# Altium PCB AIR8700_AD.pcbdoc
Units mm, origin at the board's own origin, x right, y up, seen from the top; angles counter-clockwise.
Board outline 36 x 42 mm, 2 copper layers (Top Layer, Bottom Layer); 1 components, 0 nets, 70 pads, 0 vias.
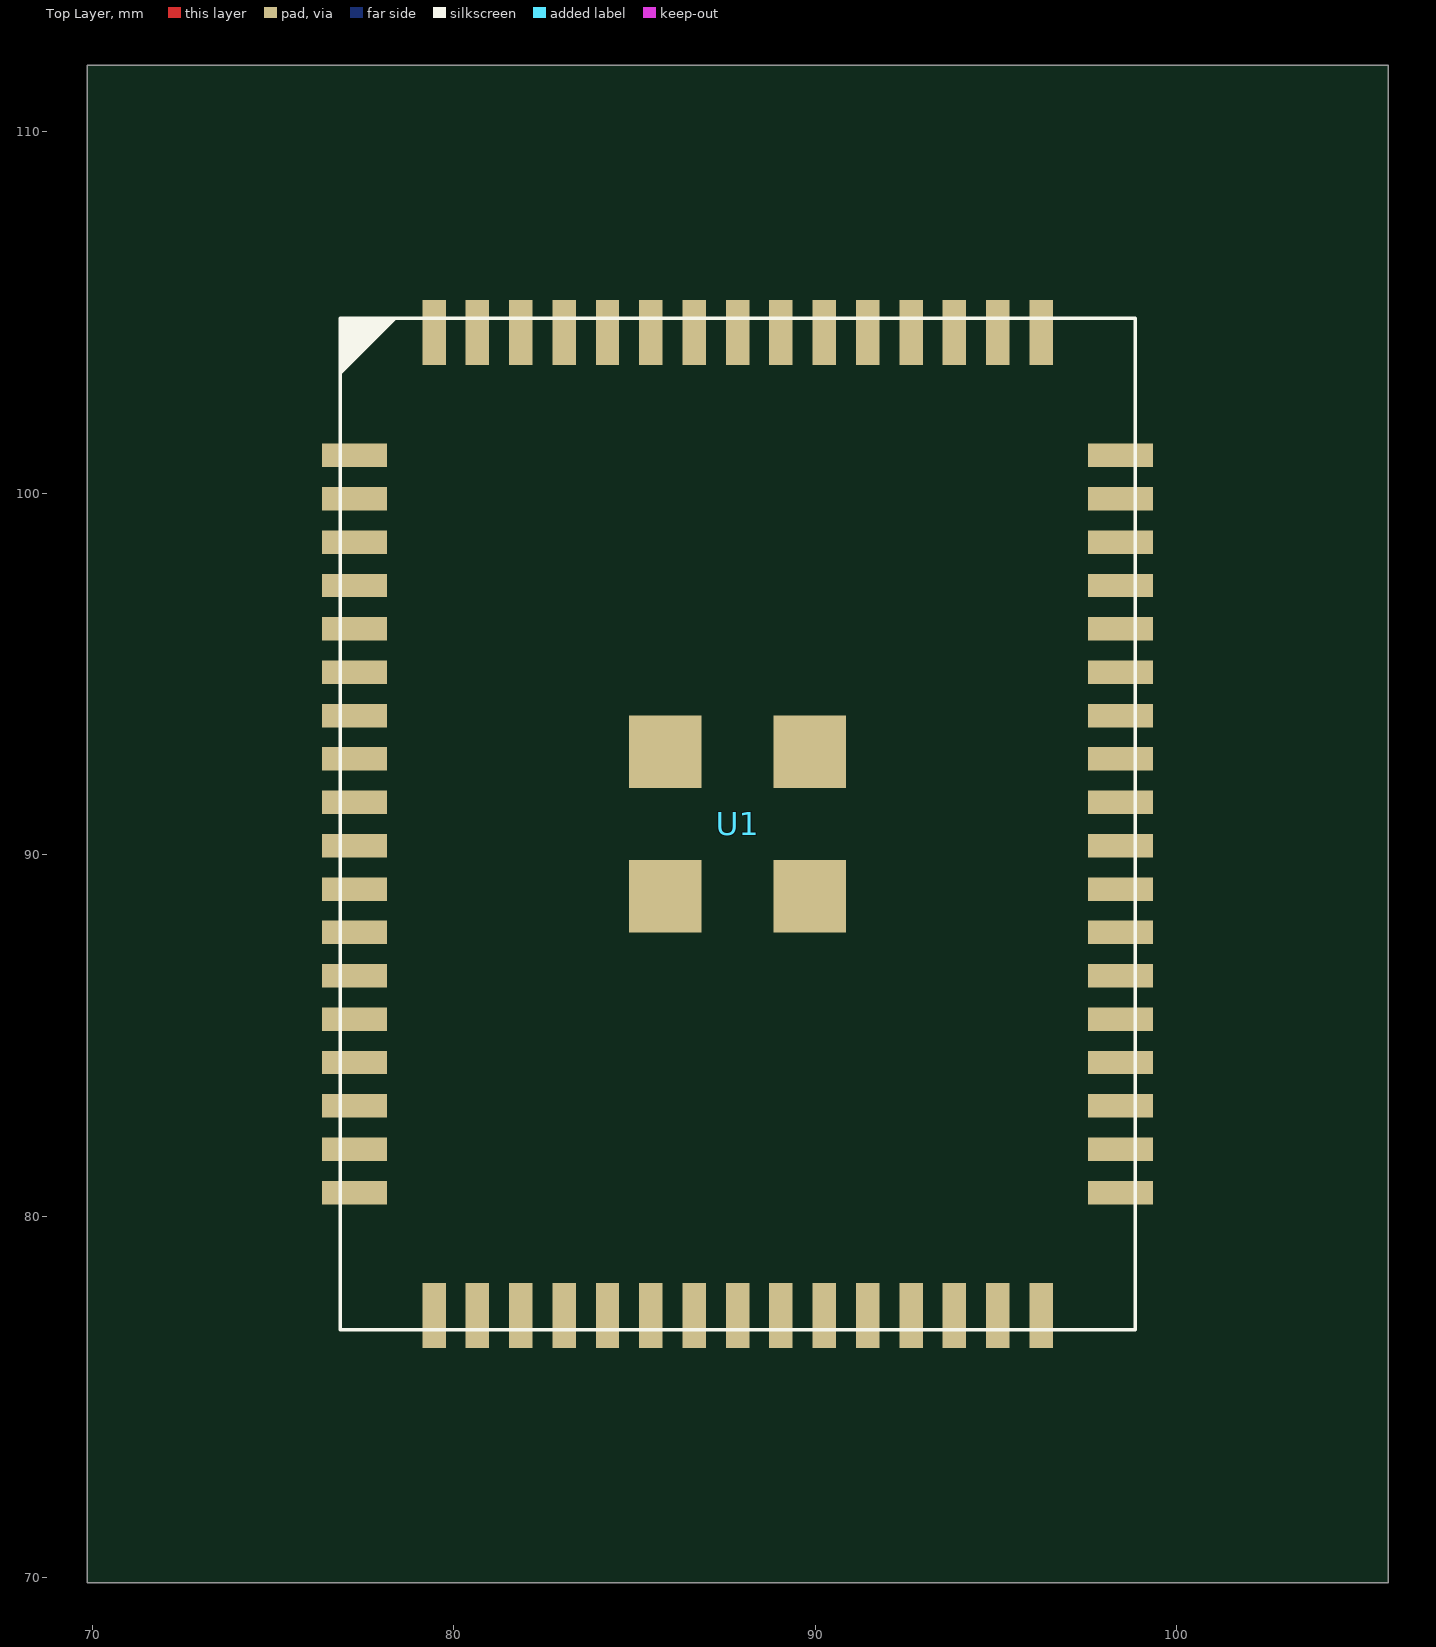
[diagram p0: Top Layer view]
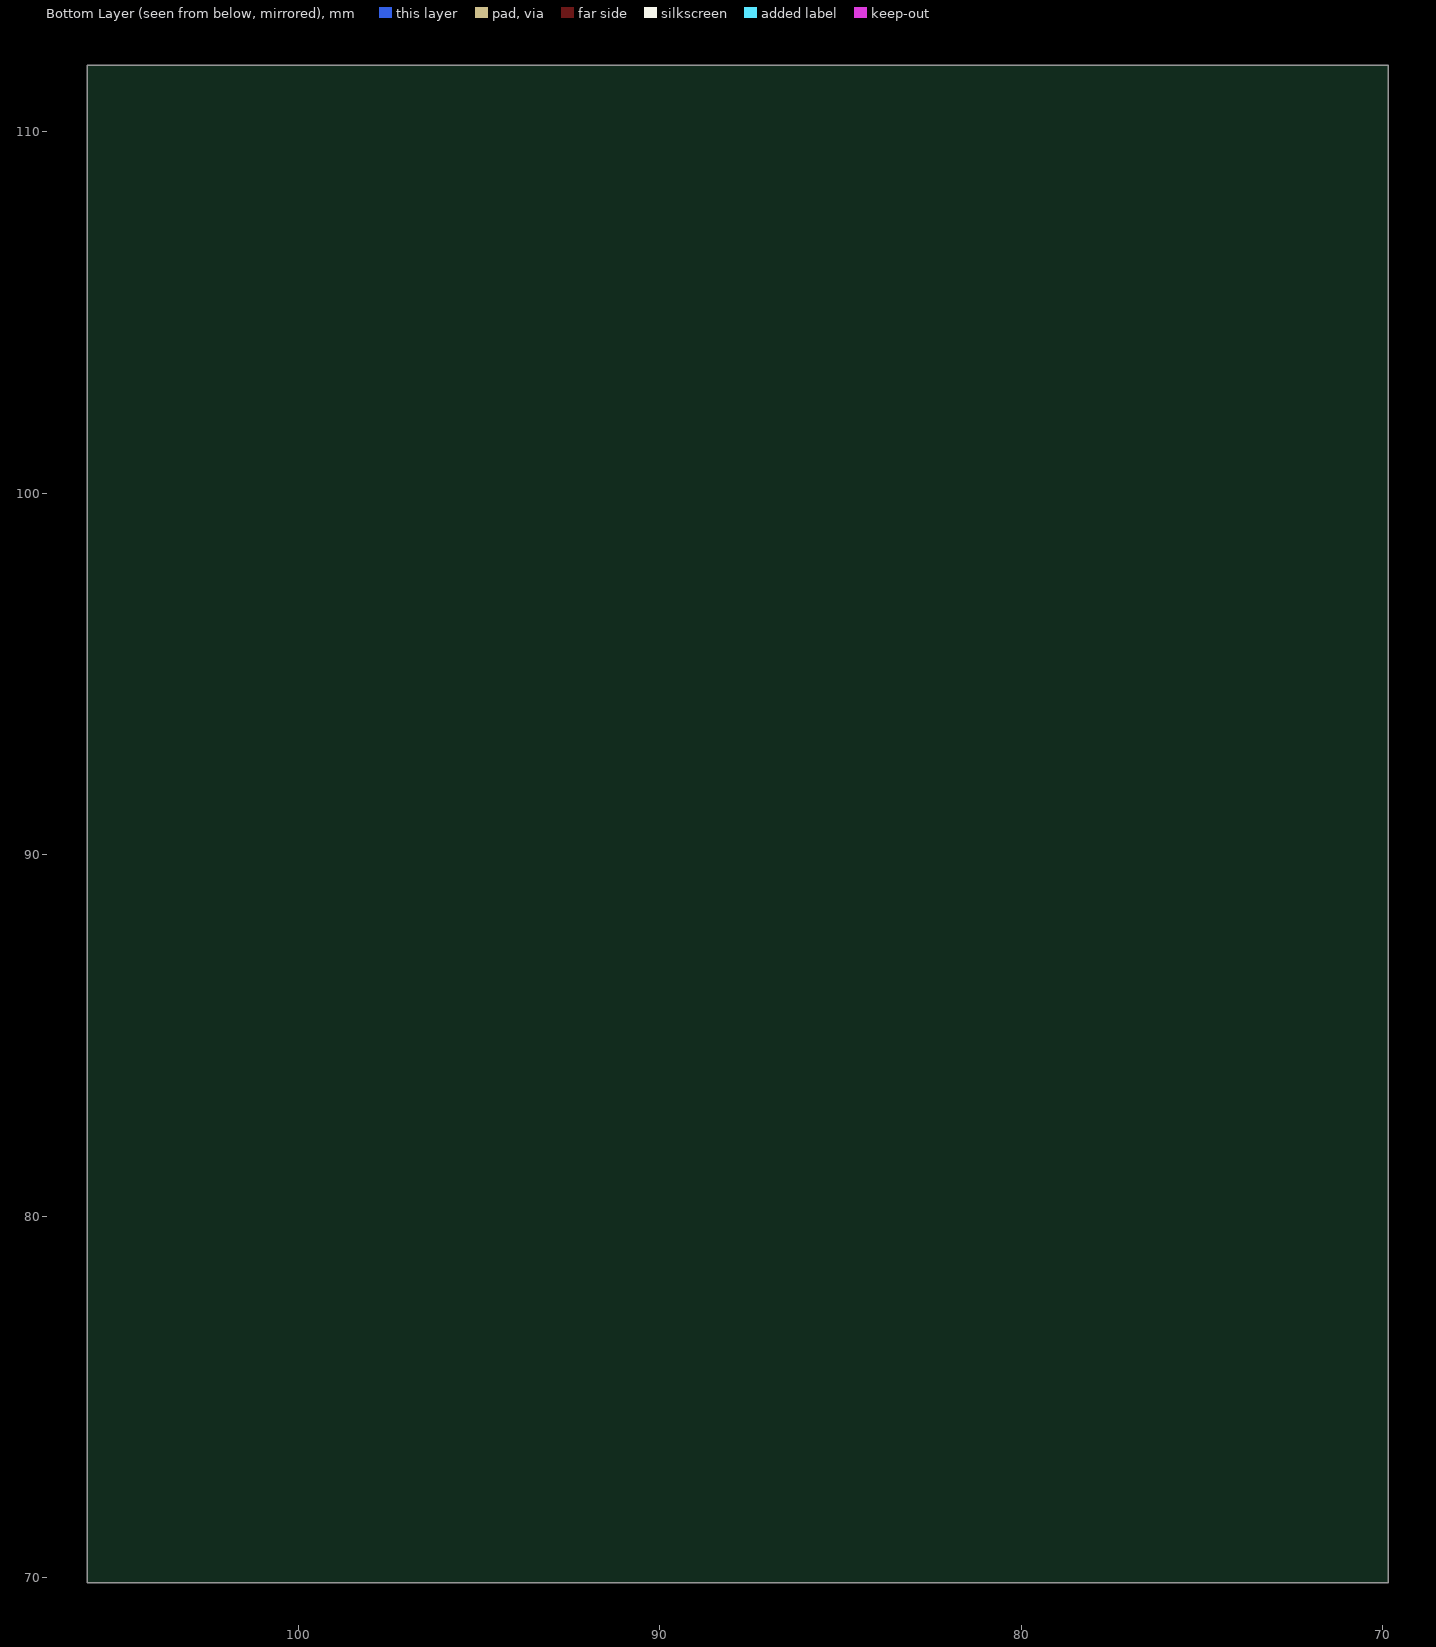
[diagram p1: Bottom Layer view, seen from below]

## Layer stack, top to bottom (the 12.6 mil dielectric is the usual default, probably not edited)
Top Layer: signal copper (thickness not stored)
Dielectric: dielectric 0.32, FR-4, Dk 4.8
Bottom Layer: signal copper (thickness not stored)

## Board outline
105.85,69.85 69.85,69.85 69.85,111.85 105.85,111.85

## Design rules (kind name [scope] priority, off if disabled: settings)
BoardOutlineClearance safeClearance [All] p0: genericclearance=0.254 ignorepadtopadclearanceinfootprint=FALSE except(0: Region-OutlineEdge Poly-OutlineEdge Text-OutlineEdge Sheet-OutlineEdge Hole-OutlineEdge Track-CutoutEdge SMDPad-CutoutEdge THPad-CutoutEdge Via-CutoutEdge Fill-CutoutEdge Region-CutoutEdge Poly-CutoutEdge Text-CutoutEdge Sheet-CutoutEdge Hole-CutoutEdge Arc-SplitContinuation Track-SplitContinuation SMDPad-SplitContinuation THPad-SplitContinuation Via-SplitContinuation Fill-SplitContinuation Poly-SplitContinuation Region-SplitContinuation Text-SplitContinuation; 0.152: Track-OutlineEdge SMDPad-OutlineEdge THPad-OutlineEdge Via-OutlineEdge Fill-OutlineEdge)
Clearance safeClearance [All] p1: gap=0.178 ignorepadtopadclearanceinfootprint=FALSE except(0: Region-Track Poly-Track Region-SMDPad Poly-SMDPad Region-THPad Poly-THPad Region-Via Poly-Via Region-Fill Poly-Fill Text-Fill Track-Region SMDPad-Region THPad-Region Via-Region Fill-Region Region-Region Poly-Region Text-Region Sheet-Region Hole-Region Track-Poly SMDPad-Poly THPad-Poly Via-Poly Fill-Poly Region-Poly Poly-Poly Text-Poly Sheet-Poly Hole-Poly Fill-Text Region-Text Poly-Text Text-Text Sheet-Text Hole-Text Region-Sheet Poly-Sheet Text-Sheet Sheet-Sheet Hole-Sheet Region-Hole Poly-Hole Text-Hole Sheet-Hole; 0.152: Track-Track SMDPad-Track THPad-Track Via-Track Fill-Track Text-Track Sheet-Track Hole-Track Track-SMDPad SMDPad-SMDPad THPad-SMDPad Via-SMDPad Fill-SMDPad Text-SMDPad Sheet-SMDPad Hole-SMDPad Track-THPad SMDPad-THPad THPad-THPad Via-THPad Fill-THPad Text-THPad Sheet-THPad Hole-THPad Track-Via SMDPad-Via THPad-Via Via-Via Fill-Via Text-Via Sheet-Via Hole-Via Track-Fill SMDPad-Fill THPad-Fill Via-Fill Fill-Fill Sheet-Fill Hole-Fill Track-Text SMDPad-Text THPad-Text Via-Text Track-Sheet SMDPad-Sheet THPad-Sheet Via-Sheet Fill-Sheet Track-Hole SMDPad-Hole THPad-Hole Via-Hole Fill-Hole Hole-Hole)
PasteMaskExpansion Common [All] p1: expansion=0
SolderMaskExpansion Common [All] p1: useseparateexpansions=TRUE expansion=0 expansionbottom=0
Width trackWidth [All] p1: maxlimit=12 minlimit=12 preferedwidth=12

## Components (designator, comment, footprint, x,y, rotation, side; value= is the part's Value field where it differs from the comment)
U1 "AIR8700-PADS" AIR8700-PADS 87.85,90.85 r0 top

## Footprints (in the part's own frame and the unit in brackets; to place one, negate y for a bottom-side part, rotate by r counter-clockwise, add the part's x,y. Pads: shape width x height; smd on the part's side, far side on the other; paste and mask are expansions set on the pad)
AIR8700-PADS [mm]
  rect 1.8x0.65 smd: 1(-10.6,10.2) 2(-10.6,9) 3(-10.6,7.8) 4(-10.6,6.6) 5(-10.6,5.4) 6(-10.6,4.2) 7(-10.6,3) 8(-10.6,1.8) 9(-10.6,0.6) 10(-10.6,-0.6) 11(-10.6,-1.8) 12(-10.6,-3) 13(-10.6,-4.2) 14(-10.6,-5.4) 15(-10.6,-6.6) 16(-10.6,-7.8) 17(-10.6,-9) 18(-10.6,-10.2) 34(10.6,-10.2) 35(10.6,-9) 36(10.6,-7.8) 37(10.6,-6.6) 38(10.6,-5.4) 39(10.6,-4.2) 40(10.6,-3) 41(10.6,-1.8) 42(10.6,-0.6) 43(10.6,0.6) 44(10.6,1.8) 45(10.6,3) 46(10.6,4.2) 47(10.6,5.4) 48(10.6,6.6) 49(10.6,7.8) 50(10.6,9) 51(10.6,10.2)
  rect 0.65x1.8 smd: 19(-8.4,-13.6) 20(-7.2,-13.6) 21(-6,-13.6) 22(-4.8,-13.6) 23(-3.6,-13.6) 24(-2.4,-13.6) 25(-1.2,-13.6) 26(0,-13.6) 27(1.2,-13.6) 28(2.4,-13.6) 29(3.6,-13.6) 30(4.8,-13.6) 31(6,-13.6) 32(7.2,-13.6) 33(8.4,-13.6) 52(8.4,13.6) 53(7.2,13.6) 54(6,13.6) 55(4.8,13.6) 56(3.6,13.6) 57(2.4,13.6) 58(1.2,13.6) 59(0,13.6) 60(-1.2,13.6) 61(-2.4,13.6) 62(-3.6,13.6) 63(-4.8,13.6) 64(-6,13.6) 65(-7.2,13.6) 66(-8.4,13.6)
  rect 2x2 smd: 67(-2,2) 68(-2,-2) 69(2,-2) 70(2,2)
  silkscreen extent -11.01,-14 11,14.02

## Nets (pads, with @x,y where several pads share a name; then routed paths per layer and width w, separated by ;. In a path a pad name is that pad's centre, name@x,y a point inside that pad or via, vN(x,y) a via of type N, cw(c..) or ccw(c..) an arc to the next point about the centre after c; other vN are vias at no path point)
pads on no net: U1.1 U1.2 U1.3 U1.4 U1.5 U1.6 U1.7 U1.8 U1.9 U1.10 U1.11 U1.12 U1.13 U1.14 U1.15 U1.16 U1.17 U1.18 U1.19 U1.20 U1.21 U1.22 U1.23 U1.24 U1.25 U1.26 U1.27 U1.28 U1.29 U1.30 U1.31 U1.32 U1.33 U1.34 U1.35 U1.36 U1.37 U1.38 U1.39 U1.40 U1.41 U1.42 U1.43 U1.44 U1.45 U1.46 U1.47 U1.48 U1.49 U1.50 U1.51 U1.52 U1.53 U1.54 U1.55 U1.56 U1.57 U1.58 U1.59 U1.60 U1.61 U1.62 U1.63 U1.64 U1.65 U1.66 U1.67 U1.68 U1.69 U1.70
